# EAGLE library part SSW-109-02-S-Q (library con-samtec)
THROUGH-HOLE .025" SQ POST SOCKET Source: Samtec SSW.pdf
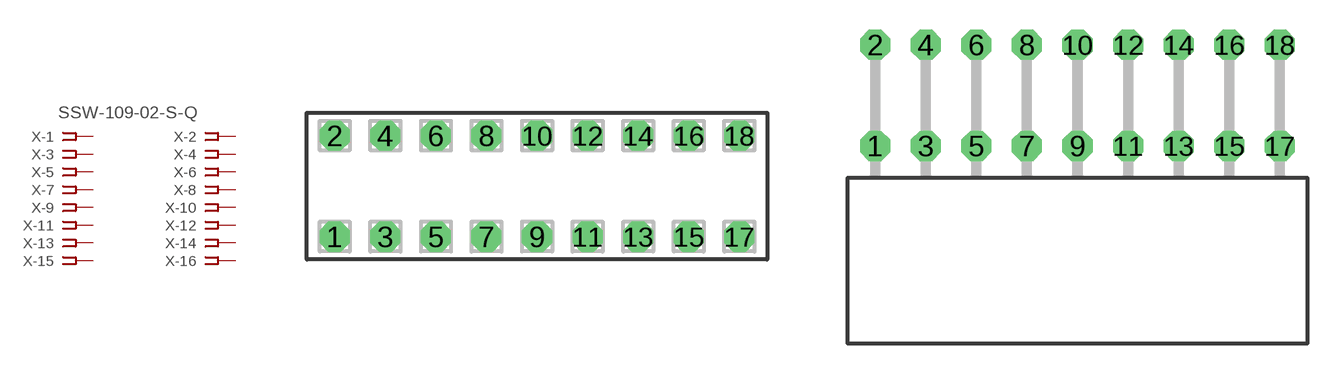
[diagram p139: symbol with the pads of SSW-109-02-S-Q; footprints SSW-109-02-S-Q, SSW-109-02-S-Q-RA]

Designator prefix X; gates -1=FPINV -2=FPIN -3=FPIN -4=FPIN -5=FPIN -6=FPIN -7=FPIN -8=FPIN -9=FPIN -10=FPIN -11=FPIN -12=FPIN -13=FPIN -14=FPIN -15=FPIN -16=FPIN -17=FPIN -18=FPIN

## SSW-109-02-S-Q (MPN: SSW-109-02-S-Q; OC_FARNELL: unknown; OC_NEWARK: 82P4798)  [SSW-109-02-S-Q]
1  -1:1  pas
2  -2:1  pas
3  -3:1  pas
4  -4:1  pas
5  -5:1  pas
6  -6:1  pas
7  -7:1  pas
8  -8:1  pas
9  -9:1  pas
10  -10:1  pas
11  -11:1  pas
12  -12:1  pas
13  -13:1  pas
14  -14:1  pas
15  -15:1  pas
16  -16:1  pas
17  -17:1  pas
18  -18:1  pas

## SSW-109-02-S-QRA (MPN: SSW-109-02-S-Q-RA; OC_FARNELL: unknown; OC_NEWARK: 82P4799)  [SSW-109-02-S-Q-RA]
Pads as for SSW-109-02-S-Q

## Footprint SSW-109-02-S-Q (pad centres in mm)
THROUGH-HOLE .025" SQ POST SOCKET Source: Samtec SSW.pdf
drill 1 pad 1.5 octagon: 1 -10.16,-2.54; 2 -10.16,2.54; 3 -7.62,-2.54; 4 -7.62,2.54; 5 -5.08,-2.54; 6 -5.08,2.54; 7 -2.54,-2.54; 8 -2.54,2.54; 9 0,-2.54; 10 0,2.54; 11 2.54,-2.54; 12 2.54,2.54; 13 5.08,-2.54; 14 5.08,2.54; 15 7.62,-2.54; 16 7.62,2.54; 17 10.16,-2.54; 18 10.16,2.54

## Footprint SSW-109-02-S-Q-RA (pad centres in mm)
THROUGH-HOLE .025" SQ POST SOCKET Source: Samtec SSW.pdf
drill 1 pad 1.5 octagon: 1 -10.16,1.524; 2 -10.16,6.604; 3 -7.62,1.524; 4 -7.62,6.604; 5 -5.08,1.524; 6 -5.08,6.604; 7 -2.54,1.524; 8 -2.54,6.604; 9 0,1.524; 10 0,6.604; 11 2.54,1.524; 12 2.54,6.604; 13 5.08,1.524; 14 5.08,6.604; 15 7.62,1.524; 16 7.62,6.604; 17 10.16,1.524; 18 10.16,6.604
